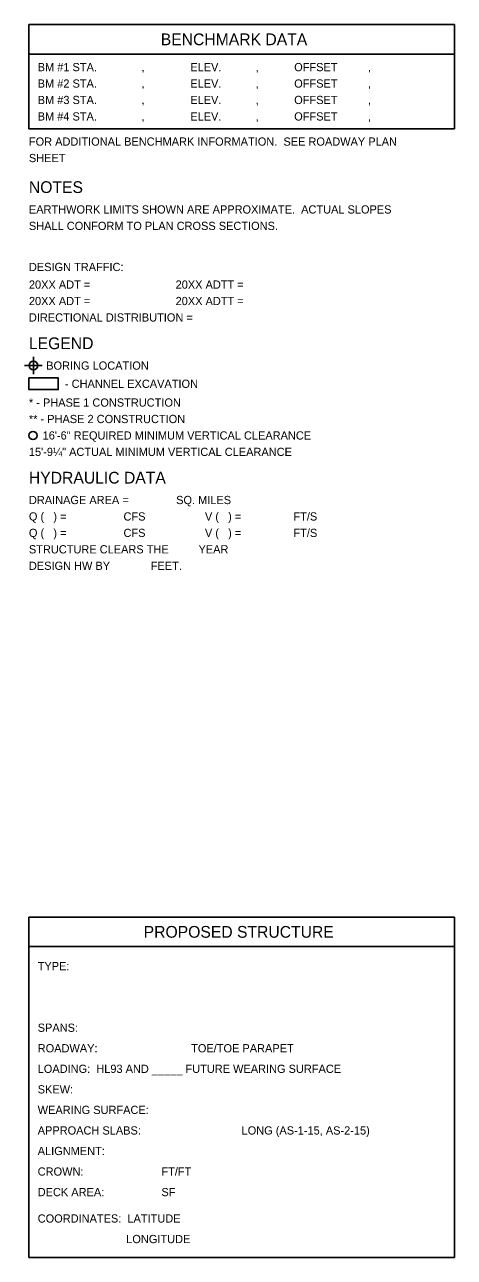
# Model space of a CAD drawing. Extents: x 0 to 1055, y 0 to 220.
# Drawn here: x 496 to 569.2, y 5 to 215 of the extents above; entities that cross this region are included whole.
import ezdxf

# ---------------------------------------------------------------- set-up
doc = ezdxf.new("R2010")
doc.units = 0
doc.layers.add('BR_P_Brg_Centerline', color=7, linetype='Continuous')
doc.layers.add('MT_P_Work_Area', color=7, linetype='Continuous')

msp = doc.modelspace()

# ---------------------------------------------------------------- linework, layer by layer
at = {"layer": 'BR_P_Brg_Centerline'}
for p, q in [((496.71, 210), (569.21, 210)), ((569.21, 57.95), (496.71, 57.95))]:
    msp.add_line(p, q, dxfattribs=at)
for points in [[(569.21, 215), (496.71, 215), (496.71, 197.27), (569.21, 197.27)], [(496.71, 154.82), (501.71, 154.82), (501.71, 152.82), (496.71, 152.82)], [(496.71, 62.95), (569.21, 62.95), (569.21, 5), (496.71, 5)]]:
    msp.add_lwpolyline(points, close=True, dxfattribs=at)
msp.add_circle((497.41, 145.01), 0.7, dxfattribs=at)
at = {"layer": 'MT_P_Work_Area'}
for p, q in [((497.48, 156.93), (497.48, 158.43)), ((497.48, 157.68), (497.48, 156.93)), ((497.48, 156.93), (495.98, 156.93)), ((497.48, 156.93), (496.73, 156.93)), ((497.48, 156.93), (497.48, 155.43)), ((497.48, 156.93), (498.98, 156.93)), ((497.48, 156.18), (497.48, 156.93)), ((497.48, 156.93), (498.23, 156.93))]:
    msp.add_line(p, q, dxfattribs=at)
msp.add_circle((497.48, 156.93), 0.75, dxfattribs=at)
for start, end in [(90, 180), (270, 360)]:
    msp.add_arc((497.48, 156.93), 0.75, start, end, dxfattribs=at)

# ---------------------------------------------------------------- texts
at = {"layer": 'BR_P_Brg_Centerline'}
for s, height, p in [('BENCHMARK DATA', 2, (519.18, 211.5)), ('BM #1 STA.', 1.4, (498.21, 207.07)), ('ELEV.', 1.4, (524.21, 207.07)), ('OFFSET', 1.4, (541.92, 207.07)), ('         ,', 1.4, (511.21, 207.07)), ('       ,', 1.4, (531.71, 207.07)), ('      ,', 1.4, (551.36, 207.07)), ('BM #2 STA.', 1.4, (498.21, 204.27)), ('         ,', 1.4, (511.21, 204.27)), ('ELEV.', 1.4, (524.21, 204.27)), ('       ,', 1.4, (531.71, 204.27)), ('OFFSET', 1.4, (541.92, 204.27)), ('      ,', 1.4, (551.36, 204.27)), ('BM #3 STA.', 1.4, (498.21, 201.47)), ('         ,', 1.4, (511.21, 201.47)), ('ELEV.', 1.4, (524.21, 201.47)), ('       ,', 1.4, (531.71, 201.47)), ('OFFSET', 1.4, (541.92, 201.47)), ('      ,', 1.4, (551.36, 201.47)), ('BM #4 STA.', 1.4, (498.21, 198.67)), ('ELEV.', 1.4, (524.21, 198.67)), ('OFFSET', 1.4, (541.92, 198.67)), ('         ,', 1.4, (511.21, 198.67)), ('       ,', 1.4, (531.71, 198.67)), ('      ,', 1.4, (551.36, 198.67)), ('FOR ADDITIONAL BENCHMARK INFORMATION.  SEE ROADWAY PLAN', 1.4, (496.71, 194.38)), ('SHEET      ', 1.4, (496.71, 191.58)), ('NOTES', 2, (496.71, 186.32)), ('EARTHWORK LIMITS SHOWN ARE APPROXIMATE.  ACTUAL SLOPES', 1.4, (496.71, 182.82)), ('SHALL CONFORM TO PLAN CROSS SECTIONS.', 1.4, (496.71, 180.02)), ('DESIGN TRAFFIC:', 1.4, (496.71, 173.02)), ('20XX ADT =', 1.4, (496.71, 170.02)), ('20XX ADTT =', 1.4, (521.71, 170.02)), ('20XX ADT =', 1.4, (496.71, 167.22)), ('20XX ADTT =', 1.4, (521.71, 167.22)), ('DIRECTIONAL DISTRIBUTION =', 1.4, (496.71, 164.42)), ('LEGEND', 2, (496.71, 159.72)), ('BORING LOCATION', 1.4, (499.66, 156.22)), ('- CHANNEL EXCAVATION', 1.4, (502.85, 153.12)), ('* - PHASE 1 CONSTRUCTION', 1.4, (496.71, 149.92)), ('** - PHASE 2 CONSTRUCTION', 1.4, (496.71, 147.12)), ('HYDRAULIC DATA', 2, (496.71, 136.82)), ('DRAINAGE AREA =', 1.4, (496.71, 133.32)), ('SQ. MILES', 1.4, (521.8, 133.32)), ('Q (   ) =', 1.4, (496.71, 130.52)), ('      CFS', 1.4, (509.71, 130.52)), ('V (   ) =', 1.4, (526.71, 130.52)), ('    FT/S', 1.4, (539.71, 130.52)), ('Q (   ) =', 1.4, (496.71, 127.72)), ('      CFS', 1.4, (509.71, 127.72)), ('V (   ) =', 1.4, (526.71, 127.72)), ('    FT/S', 1.4, (539.71, 127.72)), ('STRUCTURE CLEARS THE', 1.4, (496.71, 124.92)), ('YEAR', 1.4, (525.61, 124.92)), ('DESIGN HW BY', 1.4, (496.71, 122.12)), ('FEET.', 1.4, (517.48, 122.12)), ('PROPOSED STRUCTURE', 2, (516.27, 59.45)), ('TYPE:', 1.4, (498.21, 53.92)), ('SPANS:', 1.4, (498.21, 43.42)), ('ROADWAY:', 1.4, (498.21, 39.92)), ('TOE/TOE PARAPET', 1.4, (524.36, 39.92)), ('LOADING:  HL93 AND _____ FUTURE WEARING SURFACE', 1.4, (498.21, 36.42)), ('SKEW:', 1.4, (498.21, 32.92)), ('WEARING SURFACE:', 1.4, (498.21, 29.42)), ('APPROACH SLABS:', 1.4, (498.21, 25.92)), ('LONG (AS-1-15, AS-2-15)', 1.4, (532.95, 25.92)), ('ALIGNMENT:', 1.4, (498.21, 22.42)), ('CROWN:', 1.4, (498.21, 18.92)), ('FT/FT', 1.4, (519.29, 18.92)), ('DECK AREA:', 1.4, (498.21, 15.42)), ('SF', 1.4, (519.29, 15.42)), ('COORDINATES:  LATITUDE', 1.4, (498.21, 10.92)), ('                             LONGITUDE', 1.4, (498.21, 7.42))]:
    msp.add_text(s, height=height, dxfattribs=at).set_placement(p)
for s, p in [('16\'-6" REQUIRED MINIMUM VERTICAL CLEARANCE', (499.05, 144.32)), ('15\'-9¼" ACTUAL MINIMUM VERTICAL CLEARANCE', (496.71, 141.52))]:
    msp.add_text(s, height=1.4, rotation=0, dxfattribs=at).set_placement(p)

doc.saveas('drawing.dxf')
